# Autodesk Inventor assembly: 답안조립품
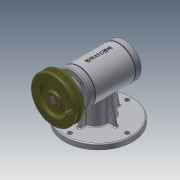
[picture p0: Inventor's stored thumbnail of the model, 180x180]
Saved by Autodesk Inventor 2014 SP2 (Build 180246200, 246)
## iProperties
Created: 2018-06
Part Number: 답안조립품
Document SubType Name: Assembly
Designer: 거성
Mass: 2015.59 g
Surface Area: 1535.41 cm^2
Volume: 512.705 cm^3
Density: 3.93129 g/cm^3
Author: 거성
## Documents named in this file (18)
- C:\Users\거성\Desktop\380608V1004\답안조립품.iam
- C:\Users\거성\Desktop\380608V1004\본체.ipt
- C:\Users\거성\Desktop\380608V1004\V-벨트풀리.ipt
- C:\Users\거성\Desktop\380608V1004\개스킷.ipt
- C:\Users\거성\Desktop\380608V1004\뒤커버.ipt
- C:\Users\거성\Desktop\380608V1004\멈춤나사 M3x8.ipt
- C:\Users\거성\Desktop\380608V1004\베어링 6201.ipt
- C:\Users\거성\Desktop\380608V1004\베어링 6202.ipt
- C:\Users\거성\Desktop\380608V1004\본체커버.ipt
- C:\Users\거성\Desktop\380608V1004\볼트 M3x0.5x8.ipt
- C:\Users\거성\Desktop\380608V1004\슬라이드.ipt
- C:\Users\거성\Desktop\380608V1004\앞커버.ipt
- C:\Users\거성\Desktop\380608V1004\오일 실 12 22 7.ipt
- 오일 실 12 22 7.ipt
- C:\Users\거성\Desktop\380608V1004\키 4x4x18.ipt
- 키 4x4x18.ipt
- C:\Users\거성\Desktop\380608V1004\편심축.ipt
- C:\Users\거성\Desktop\380608V1004\가변스프링.ipt
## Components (4 placed, 3 different names)
1. V-벨트풀리:1 — 각도:2
2. 개스킷:1
3. 개스킷:2
4. 가변스프링:1
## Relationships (1: Angle 1)
- 각도:2 [Angle]: V-벨트풀리:1
